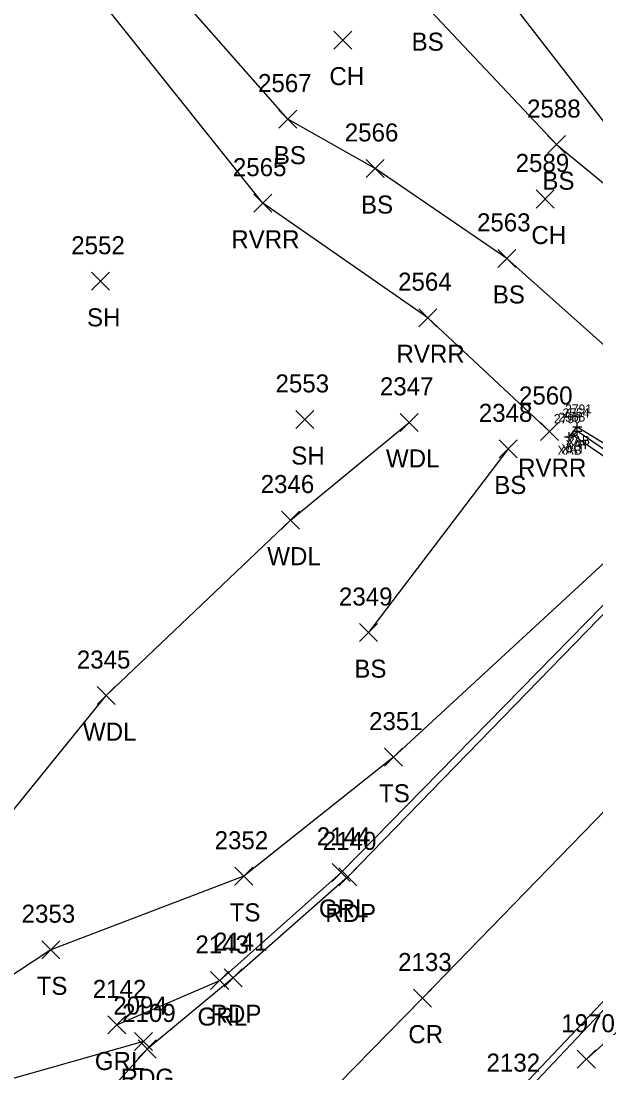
# Model space of a CAD drawing. Extents: x 1633660 to 1636532, y 388643 to 392631.
# Drawn here: x 1634668.1 to 1634731.9, y 389178.4 to 389295.1 of the extents above; entities that cross this region are included whole.
import ezdxf

# ---------------------------------------------------------------- set-up
doc = ezdxf.new("R2010")
doc.units = 0
for name, color, linetype in [('B_A', 7, 'Continuous'), ('B_I', 7, 'Continuous'), ('B_TIC', 7, 'Continuous'), ('BSUBM', 7, 'Continuous'), ('L_A', 7, 'Continuous'), ('L_I', 7, 'Continuous'), ('L_TIC', 7, 'Continuous'), ('LAWA', 7, 'Continuous'), ('LAWE', 7, 'Continuous'), ('LELB', 7, 'Continuous'), ('P_A', 7, 'Continuous'), ('P_I', 7, 'Continuous'), ('P_TIC', 7, 'Continuous'), ('PET', 7, 'Continuous'), ('PEU', 7, 'Continuous'), ('PRC', 7, 'Continuous'), ('R_A', 7, 'Continuous'), ('R_I', 7, 'Continuous'), ('R_TIC', 7, 'Continuous'), ('RGR', 7, 'Continuous')]:
    doc.layers.add(name, color=color, linetype=linetype)

msp = doc.modelspace()

# ---------------------------------------------------------------- linework, layer by layer
at = {"layer": 'B_TIC'}
for p, q in [((1634729.84, 389250.1), (1634729.91, 389250.1)), ((1634728.92, 389249.02), (1634729, 389249.02)), ((1634729.37, 389249.19), (1634729.45, 389249.19)), ((1634729.83, 389249.65), (1634729.91, 389249.65))]:
    msp.add_line(p, q, dxfattribs=at)
for points in [[(1634729.34, 389250.1), (1634730.34, 389250.1)], [(1634729.83, 389249.15), (1634729.83, 389250.15)], [(1634729.84, 389249.6), (1634729.84, 389250.6)], [(1634728.42, 389249.02), (1634729.42, 389249.02)], [(1634728.87, 389249.19), (1634729.87, 389249.19)], [(1634728.92, 389248.52), (1634728.92, 389249.52)], [(1634729.33, 389249.65), (1634730.33, 389249.65)], [(1634729.37, 389248.69), (1634729.37, 389249.69)]]:
    msp.add_lwpolyline(points, dxfattribs=at)
at = {"layer": 'BSUBM'}
for points in [[(1634728.92, 389249.02), (1634729.84, 389250.1), (1634742.14, 389242.62), (1634746.67, 389240.04), (1634765.79, 389221.1)], [(1634729.83, 389249.65), (1634729.37, 389249.19), (1634739.89, 389242.01), (1634742.06, 389240.59), (1634742.53, 389241.11), (1634740.27, 389242.54)], [(1634740.27, 389242.54), (1634729.83, 389249.65)]]:
    msp.add_lwpolyline(points, dxfattribs=at)
at = {"layer": 'L_TIC'}
for points in [[(1634702.82, 389292.02), (1634704.82, 389294.02)], [(1634704.82, 389292.02), (1634702.82, 389294.02)], [(1634696.7, 389283.25), (1634698.7, 389285.25)], [(1634698.7, 389283.25), (1634696.7, 389285.25)], [(1634726.52, 389280.42), (1634728.52, 389282.42)], [(1634728.52, 389280.42), (1634726.52, 389282.42)], [(1634706.38, 389277.77), (1634708.38, 389279.77)], [(1634708.38, 389277.77), (1634706.38, 389279.77)], [(1634693.91, 389273.92), (1634695.91, 389275.92)], [(1634695.91, 389273.92), (1634693.91, 389275.92)], [(1634725.26, 389274.39), (1634727.26, 389276.39)], [(1634727.26, 389274.39), (1634725.26, 389276.39)], [(1634721.01, 389267.8), (1634723.01, 389269.8)], [(1634723.01, 389267.8), (1634721.01, 389269.8)], [(1634675.91, 389265.26), (1634677.91, 389267.26)], [(1634677.91, 389265.26), (1634675.91, 389267.26)], [(1634712.25, 389261.22), (1634714.25, 389263.22)], [(1634714.25, 389261.22), (1634712.25, 389263.22)], [(1634698.59, 389249.93), (1634700.59, 389251.93)], [(1634700.59, 389249.93), (1634698.59, 389251.93)], [(1634710.18, 389249.61), (1634712.18, 389251.61)], [(1634712.18, 389249.61), (1634710.18, 389251.61)], [(1634725.75, 389248.59), (1634727.75, 389250.59)], [(1634727.75, 389248.59), (1634725.75, 389250.59)], [(1634721.16, 389246.67), (1634723.16, 389248.67)], [(1634723.16, 389246.67), (1634721.16, 389248.67)], [(1634696.99, 389238.77), (1634698.99, 389240.77)], [(1634698.99, 389238.77), (1634696.99, 389240.77)], [(1634705.64, 389226.29), (1634707.64, 389228.29)], [(1634707.64, 389226.29), (1634705.64, 389228.29)], [(1634676.53, 389219.3), (1634678.53, 389221.3)], [(1634678.53, 389219.3), (1634676.53, 389221.3)], [(1634708.42, 389212.47), (1634710.42, 389214.47)], [(1634710.42, 389212.47), (1634708.42, 389214.47)], [(1634691.83, 389199.26), (1634693.83, 389201.26)], [(1634693.83, 389199.26), (1634691.83, 389201.26)], [(1634670.4, 389191.11), (1634672.4, 389193.11)], [(1634672.4, 389191.11), (1634670.4, 389193.11)], [(1634729.84, 389178.96), (1634731.84, 389180.96)], [(1634731.84, 389178.96), (1634729.84, 389180.96)]]:
    msp.add_lwpolyline(points, dxfattribs=at)
at = {"layer": 'LAWA'}
msp.add_lwpolyline([(1634638.03, 389193.98), (1634658.26, 389196.58), (1634677.53, 389220.3), (1634697.99, 389239.77), (1634711.18, 389250.61)], dxfattribs=at)
at = {"layer": 'LAWE'}
for points in [[(1634748.89, 389270.78), (1634735.19, 389280.87), (1634720.26, 389300.16), (1634697.78, 389320.61), (1634664.26, 389355.51), (1634647.22, 389374.92)], [(1634726.75, 389249.59), (1634713.25, 389262.22), (1634694.91, 389274.92), (1634673.59, 389301.63), (1634663.85, 389313.71), (1634641.14, 389330.24), (1634625.58, 389344.61)]]:
    msp.add_lwpolyline(points, dxfattribs=at)
at = {"layer": 'LELB'}
for points in [[(1634641.71, 389371.13), (1634664.46, 389349.91), (1634678.27, 389333.06), (1634696, 389315.41), (1634713, 389296.84), (1634727.52, 389281.42), (1634745.22, 389266.89), (1634752.92, 389261.93)], [(1634742.97, 389244.48), (1634736.28, 389256.06), (1634722.01, 389268.8), (1634707.38, 389278.77), (1634697.7, 389284.25), (1634680.66, 389303.58), (1634664.36, 389319.39), (1634645.08, 389331.2), (1634628.27, 389346.62)], [(1634722.16, 389247.67), (1634706.64, 389227.29)], [(1634738.57, 389240.32), (1634709.42, 389213.47), (1634692.83, 389200.26), (1634671.4, 389192.11), (1634646.09, 389175.45)], [(1634764.11, 389212.13), (1634749.45, 389196.63), (1634730.84, 389179.96)]]:
    msp.add_lwpolyline(points, dxfattribs=at)
at = {"layer": 'P_TIC'}
for points in [[(1634703.36, 389199.19), (1634705.36, 389201.19)], [(1634705.36, 389199.19), (1634703.36, 389201.19)], [(1634690.63, 389188.01), (1634692.63, 389190.01)], [(1634692.63, 389188.01), (1634690.63, 389190.01)], [(1634711.64, 389185.75), (1634713.64, 389187.75)], [(1634713.64, 389185.75), (1634711.64, 389187.75)], [(1634680.66, 389180.92), (1634682.66, 389182.92)], [(1634682.66, 389180.92), (1634680.66, 389182.92)], [(1634681.08, 389180.1), (1634683.08, 389182.1)], [(1634683.08, 389180.1), (1634681.08, 389182.1)]]:
    msp.add_lwpolyline(points, dxfattribs=at)
at = {"layer": 'PET'}
for points in [[(1634682.08, 389181.1), (1634650.7, 389146.38), (1634620.25, 389115.23), (1634604.63, 389098.3), (1634579.1, 389070.12), (1634546.56, 389039.3), (1634509.68, 389006.46), (1634474.11, 388976.77), (1634488.61, 388975.18), (1634504.36, 388973.04), (1634532.03, 388994.36), (1634563.21, 389020.04), (1634596.33, 389051.02), (1634641.93, 389096.55), (1634679.61, 389135.06), (1634705.94, 389161.6), (1634722.45, 389175.59), (1634749.3, 389203.85), (1634763.45, 389218.45), (1634753.18, 389229.52), (1634742.76, 389239.64), (1634704.36, 389200.19), (1634691.63, 389189.01)], [(1634691.63, 389189.01), (1634682.08, 389181.1)]]:
    msp.add_lwpolyline(points, dxfattribs=at)
at = {"layer": 'PEU'}
msp.add_lwpolyline([(1634681.66, 389181.92), (1634655.28, 389174.45), (1634621.42, 389148.64), (1634596.29, 389137.43), (1634576.33, 389130.43), (1634529, 389119.71), (1634497.86, 389117.98)], dxfattribs=at)
at = {"layer": 'PRC'}
msp.add_lwpolyline([(1634489.59, 388976.11), (1634524.5, 389003.94), (1634553.65, 389029.27), (1634589.65, 389062.97), (1634628.75, 389101.27), (1634671.28, 389144.58), (1634699.51, 389173.36), (1634712.64, 389186.75), (1634739.32, 389214.16), (1634752.84, 389228.98)], dxfattribs=at)
at = {"layer": 'R_TIC'}
for points in [[(1634702.61, 389199.69), (1634704.61, 389201.69)], [(1634704.61, 389199.69), (1634702.61, 389201.69)], [(1634689.13, 389187.7), (1634691.13, 389189.7)], [(1634691.13, 389187.7), (1634689.13, 389189.7)], [(1634677.73, 389182.77), (1634679.73, 389184.77)], [(1634679.73, 389182.77), (1634677.73, 389184.77)]]:
    msp.add_lwpolyline(points, dxfattribs=at)
at = {"layer": 'RGR'}
for points in [[(1634678.73, 389183.77), (1634690.13, 389188.7), (1634703.61, 389200.69), (1634741.75, 389239.54)], [(1634762.74, 389216.64), (1634741.24, 389194.43), (1634716.39, 389168.13), (1634709.54, 389158.78), (1634705.45, 389150.07)]]:
    msp.add_lwpolyline(points, dxfattribs=at)

# ---------------------------------------------------------------- texts
at = {"layer": 'B_A'}
for s, p in [('XAB', (1634728.56, 389248.1)), ('XAB', (1634727.64, 389247.02)), ('XAT', (1634728.07, 389247.19)), ('XAT', (1634728.54, 389247.65))]:
    msp.add_text(s, height=1, dxfattribs=at).set_placement(p)
at = {"layer": 'B_I'}
for s, p in [('2791', (1634728.49, 389251.6)), ('2790', (1634727.24, 389250.52)), ('2555', (1634727.74, 389250.69)), ('2554', (1634728.2, 389251.15))]:
    msp.add_text(s, height=1, dxfattribs=at).set_placement(p)
at = {"layer": 'L_A'}
for s, p in [('BS', (1634711.44, 389291.84)), ('CH', (1634702.31, 389288.02)), ('BS', (1634696.14, 389279.25)), ('BS', (1634725.96, 389276.42)), ('BS', (1634705.82, 389273.77)), ('CH', (1634724.74, 389270.39)), ('RVRR', (1634691.42, 389269.92)), ('BS', (1634720.45, 389263.8)), ('SH', (1634675.4, 389261.26)), ('RVRR', (1634709.76, 389257.22)), ('SH', (1634698.08, 389245.93)), ('WDL', (1634708.59, 389245.61)), ('RVRR', (1634723.26, 389244.59)), ('BS', (1634720.61, 389242.67)), ('WDL', (1634695.41, 389234.77)), ('BS', (1634705.08, 389222.29)), ('WDL', (1634674.95, 389215.3)), ('TS', (1634707.82, 389208.47)), ('TS', (1634691.24, 389195.26)), ('TS', (1634669.81, 389187.11))]:
    msp.add_text(s, height=2, dxfattribs=at).set_placement(p)
at = {"layer": 'L_I'}
for s, p in [('2567', (1634694.39, 389287.25)), ('2588', (1634724.26, 389284.42)), ('2566', (1634704.02, 389281.77)), ('2589', (1634722.99, 389278.39)), ('2565', (1634691.6, 389277.92)), ('2563', (1634718.7, 389271.8)), ('2552', (1634673.65, 389269.26)), ('2564', (1634709.94, 389265.22)), ('2553', (1634696.33, 389253.93)), ('2347', (1634707.92, 389253.61)), ('2560', (1634723.36, 389252.59)), ('2348', (1634718.9, 389250.67)), ('2346', (1634694.68, 389242.77)), ('2349', (1634703.37, 389230.29)), ('2345', (1634674.27, 389223.3)), ('2351', (1634706.72, 389216.47)), ('2352', (1634689.57, 389203.26)), ('2353', (1634668.14, 389195.11)), ('1970', (1634728.06, 389182.96))]:
    msp.add_text(s, height=2, dxfattribs=at).set_placement(p)
at = {"layer": 'P_A'}
for s, p in [('RDP', (1634701.85, 389195.19)), ('RDP', (1634689.12, 389184.01)), ('CR', (1634711.07, 389181.75)), ('RDG', (1634679.14, 389176.92))]:
    msp.add_text(s, height=2, dxfattribs=at).set_placement(p)
at = {"layer": 'P_I'}
for s, p in [('2140', (1634701.58, 389203.19)), ('2141', (1634689.5, 389192.01)), ('2133', (1634709.94, 389189.75)), ('2094', (1634678.32, 389184.92)), ('2109', (1634679.3, 389184.1)), ('2132', (1634719.76, 389178.59))]:
    msp.add_text(s, height=2, dxfattribs=at).set_placement(p)
at = {"layer": 'R_A'}
for p in [(1634701.15, 389195.69), (1634687.67, 389183.7), (1634676.27, 389178.77)]:
    msp.add_text('GRL', height=2, dxfattribs=at).set_placement(p)
at = {"layer": 'R_I'}
for s, p in [('2144', (1634700.91, 389203.69)), ('2143', (1634687.43, 389191.7)), ('2142', (1634676.04, 389186.77))]:
    msp.add_text(s, height=2, dxfattribs=at).set_placement(p)

doc.saveas('drawing.dxf')
